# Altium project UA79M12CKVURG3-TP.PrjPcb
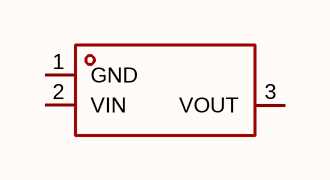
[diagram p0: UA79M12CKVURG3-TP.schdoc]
1 sheet, 1 parts. Net scope: global (net labels, ports and power ports of the same name join across sheets).

## Sheet UA79M12CKVURG3-TP.schdoc
size 127 x 101 mm

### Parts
U?  ua79m12ckvurg3-tp  [TO-252-2_L6.6-W6.1-P4.60-LS10.0-BR-CW]  (value not drawn)

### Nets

Not connected (* = marked no-connect by the designer): U? 1(GND) 2(VIN) 3(VOUT)

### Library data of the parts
U? = ua79m12ckvurg3-tp: 输出极性:负极;工作电压:35V;输出电压:12V;输出电流:500mA;电源纹波抑制比(PSRR):60dB;输出类型:固定;; Manufacturer: TECH PUBLIC(台舟); AddInBom: yes; ModelId: 2bfbfbb77002446c96d8a76a432e0188; ModelTransform: 246.80147,383.8575,0,90,0,0,-31.302,0.003,0; Output Configuration: 负极; Voltage - Supply: 35V; Output Voltage: 12V; Output Current: 500mA; Power Supply Rejection Ratio (PSRR): 60dB; Voltage Dropout: 2V@(350mA); standby current: 1.5mA; Noise: 200uV; Output Type: 固定; Number of Outputs: 1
